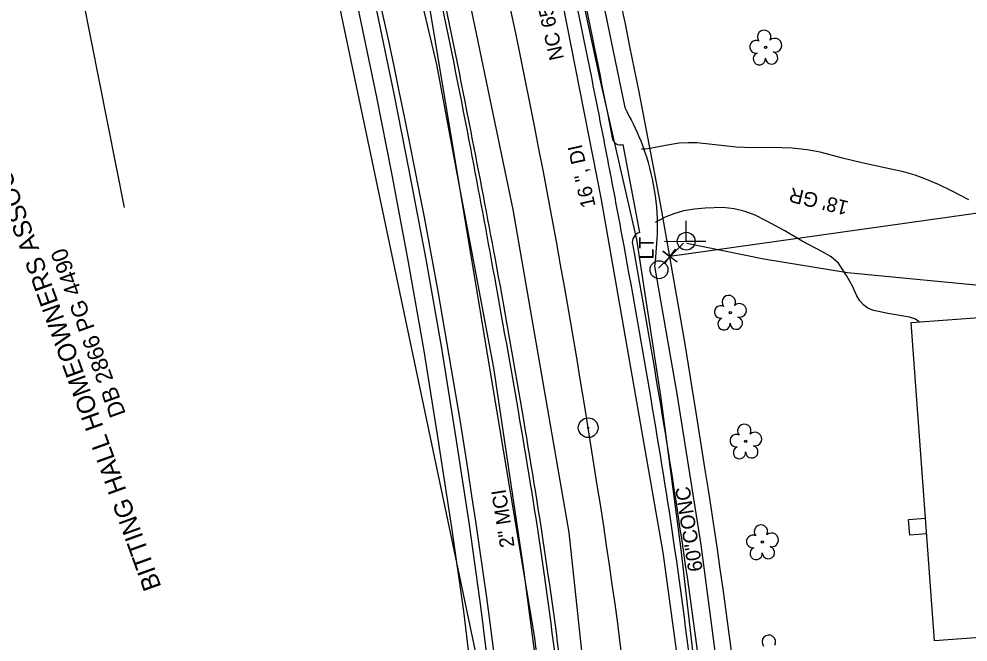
# Model space of a CAD drawing. Extents: x 1614611 to 1617571, y 898867 to 905462.
# Drawn here: x 1616509.7 to 1616770.7, y 902500.2 to 902671.5 of the extents above; entities that cross this region are included whole.
import ezdxf

# ---------------------------------------------------------------- set-up
doc = ezdxf.new("R2010")
doc.units = 0
for name, color, linetype in [('Exist Boundary Watershed Impervious C 09', 7, 'Continuous'), ('Exist Boundary Watershed Residential C 05', 7, 'Continuous'), ('Exist Building', 7, 'Continuous'), ('Exist Horizontal Alignment Tick Label', 7, 'Continuous'), ('Exist Other Culture Area Outline', 7, 'Continuous'), ('Exist Roads EOP Other Text', 7, 'Continuous'), ('Exist Roads EOP Text', 7, 'Continuous'), ('Exist Roads Soil', 7, 'Continuous'), ('Exist Roads Soil Text', 7, 'Continuous'), ('Exist Survey Centerline Point CELL', 7, 'Continuous'), ('Exist Utilities Gas UG Line SUE LOS B', 7, 'Continuous'), ('Exist Utilities Other Pole CELL', 7, 'Continuous'), ('Exist Utilities Other Pole Text', 7, 'Continuous'), ('Exist Utilities Power Joint Use Telephone CELL', 7, 'Continuous'), ('Exist Utilities Telephone UG Cable SUE LOS B', 7, 'Continuous'), ('Exist Utilities Telephone UG FO SUE LOS B', 7, 'Continuous'), ('Exist Utilities Telephone UG FO SUE LOS C', 7, 'Continuous'), ('Exist Utilities Telephone UG FO SUE LOS C Text', 7, 'Continuous'), ('Exist Utilities Water UG Line SUE LOS B', 7, 'Continuous'), ('Exist Utilities Water UG Line SUE LOS B Text', 7, 'Continuous'), ('Exist Vegetation Tree CELL', 7, 'Continuous'), ('Prop Drainage Structure Catch Basin Grate 840 03E Label', 7, 'Continuous'), ('Prop Drainage Structure Pipe Alternate 30in Label', 7, 'Continuous'), ('Prop Drainage Structure Pipe Removal', 7, 'Continuous'), ('Prop Drainage Structure Pipe Removal Label', 7, 'Continuous'), ('Prop Drainage Structure Tops and Inverts LABEL', 7, 'Continuous'), ('Prop Earthen Structure Head Ditch Label', 7, 'Continuous'), ('Raster_Level_2', 7, 'Continuous'), ('Scratch_Level_1', 7, 'Continuous'), ('Scratch_Level_9', 7, 'Continuous')]:
    doc.layers.add(name, color=color, linetype=linetype)

# ---------------------------------------------------------------- blocks, each defined once
blk = doc.blocks.new('EXIST SURVEY CENTERLINE POINT')
at = {"layer": 'Exist Survey Centerline Point CELL'}
for radius in [0.0542, 0.00375]:
    blk.add_circle((0, 0), radius, dxfattribs=at)

msp = doc.modelspace()

# ---------------------------------------------------------------- linework, layer by layer
at = {"layer": 'Exist Boundary Watershed Impervious C 09'}
msp.add_spline([(1616665.13, 902435.43), (1616660.48, 902479.08), (1616654.89, 902521.26), (1616648.51, 902561.33), (1616641.12, 902603.28), (1616634.46, 902638.28), (1616625.9, 902680.69), (1616616.67, 902721.99), (1616606.86, 902763.22), (1616596.71, 902801.99), (1616585.45, 902842.18), (1616573.19, 902881.5), (1616565.19, 902906.61), (1616557.25, 902931.31), (1616544.89, 902968.22), (1616530.94, 903009.35), (1616518.06, 903047.65)], degree=3, dxfattribs=at)
at = {"layer": 'Exist Boundary Watershed Residential C 05'}
for p, q in [((1616671.61, 902645.14), (1616672.82, 902638.84)), ((1616675.8, 902636.98), (1616680.4, 902612.79)), ((1616678.43, 902609.58), (1616678.51, 902609.27))]:
    msp.add_line(p, q, dxfattribs=at)
for centre, major_axis, ratio, start_param, end_param in [((1616675.14, 902639.25), (-2.23, -0.78), 0.999797, 6.125089, 7.800541), ((1616681.13, 902610.14), (0.88, 2.61), 0.999982, 0.589797, 2.101645)]:
    msp.add_ellipse(centre, major_axis=major_axis, ratio=ratio, start_param=start_param, end_param=end_param, dxfattribs=at)
for points in [[(1616609.89, 902892.41), (1616622.17, 902852.43), (1616633.45, 902811.75), (1616643.74, 902771.73), (1616653.39, 902730.67), (1616662.94, 902688.03), (1616671.61, 902645.14)], [(1616678.51, 902609.27), (1616685.77, 902567.51), (1616692.26, 902526.08), (1616698.01, 902483.12), (1616702.89, 902438.1)]]:
    msp.add_spline(points, degree=3, dxfattribs=at)
at = {"layer": 'Exist Building'}
msp.add_lwpolyline([(1616786.91, 902566.36), (1616791.57, 902502.74), (1616761.45, 902500.53), (1616755.04, 902588.07), (1616785.04, 902590.27), (1616785.29, 902586.87), (1616801.91, 902588.09), (1616803.42, 902567.57)], close=True, dxfattribs=at)
at = {"layer": 'Exist Other Culture Area Outline'}
msp.add_lwpolyline([(1616759.3, 902529.96), (1616754.72, 902529.58), (1616754.35, 902533.86), (1616758.98, 902534.25)], dxfattribs=at)
at = {"layer": 'Exist Roads Soil'}
for points in [[(1616770.94, 902621.8), (1616766.35, 902624.21), (1616762.63, 902626.01), (1616759.28, 902627.41), (1616756.2, 902628.57), (1616752.95, 902629.5), (1616747.81, 902630.59), (1616741.51, 902631.96), (1616736.18, 902633.25), (1616730.09, 902634.92), (1616726.5, 902635.55), (1616722.37, 902636.04), (1616716.88, 902636.18), (1616711.55, 902636.08), (1616706.93, 902636.33), (1616700.34, 902637.02), (1616696.17, 902637.47), (1616693.76, 902637.52), (1616691.23, 902637.35), (1616687.54, 902636.74), (1616683.27, 902635.95), (1616681.94, 902635.78), (1616680.92, 902635.71)], [(1616757.26, 902588.23), (1616756.23, 902588.96), (1616754.59, 902589.56), (1616748.67, 902590.59), (1616746.51, 902590.99), (1616744.72, 902591.39), (1616743.2, 902592.04), (1616742.07, 902592.8), (1616740.96, 902594.01), (1616740.11, 902595.42), (1616738.93, 902598.03), (1616737.26, 902600.97), (1616735.93, 902603.09), (1616735.06, 902604.37), (1616733.09, 902606.11), (1616730.67, 902607.47), (1616725.12, 902610.4), (1616720.34, 902613.24), (1616715.35, 902615.95), (1616712.18, 902617.57), (1616709.41, 902618.61), (1616706.41, 902619.33), (1616703.3, 902619.67), (1616698.4, 902619.56), (1616695.5, 902619.2), (1616692.46, 902618.75), (1616689.76, 902617.95), (1616687.43, 902617.03), (1616684.67, 902615.6)]]:
    msp.add_lwpolyline(points, dxfattribs=at)
at = {"layer": 'Exist Utilities Gas UG Line SUE LOS B'}
msp.add_lwpolyline([(1616661.01, 902037.25), (1616663.33, 902064.4), (1616667.18, 902120.35), (1616669.8, 902175.63), (1616670.18, 902203.89), (1616670, 902252.83), (1616667.06, 902308.42), (1616666.18, 902342.89), (1616662.96, 902384.82), (1616659.36, 902418.53), (1616657.17, 902446.04), (1616652.37, 902490.94), (1616648.49, 902520.82), (1616640.31, 902575.63), (1616630.24, 902629.08), (1616624.64, 902659), (1616610.54, 902718.34), (1616603.5, 902747.83), (1616594.95, 902779.96), (1616588.83, 902805.4), (1616574.94, 902856.71), (1616560.06, 902902.39)], dxfattribs=at)
at = {"layer": 'Exist Utilities Other Pole CELL'}
msp.add_circle((1616685.72, 902602.58), 2.46, dxfattribs=at)
at = {"layer": 'Exist Utilities Power Joint Use Telephone CELL'}
msp.add_line((1616693.21, 902610.41), (1616693.21, 902610.41), dxfattribs=at)
msp.add_lwpolyline([(1616687.27, 902610.41), (1616698.61, 902610.38), (1616693.21, 902610.4), (1616693.21, 902616.04)], dxfattribs=at)
msp.add_circle((1616693.21, 902610.42), 2.45, dxfattribs=at)
at = {"layer": 'Exist Utilities Telephone UG Cable SUE LOS B'}
msp.add_lwpolyline([(1616653.58, 902416.71), (1616663.67, 902417.14), (1616669.74, 902418.75), (1616672.64, 902421.54), (1616661.03, 902530.35), (1616645.59, 902619.16), (1616624.26, 902721.72), (1616610.21, 902784.31), (1616604.98, 902794.39), (1616600.3, 902799.85), (1616600.03, 902805.22), (1616598.01, 902825.81), (1616571.3, 902910.94), (1616549.08, 902977.64), (1616515.65, 903076.73), (1616483.43, 903168.54), (1616464.03, 903218.81), (1616463.64, 903219.2), (1616462.93, 903219.33), (1616457.94, 903217.72), (1616449, 903216.46)], dxfattribs=at)
at = {"layer": 'Exist Utilities Telephone UG FO SUE LOS B'}
msp.add_lwpolyline([(1616708.77, 902097.06), (1616709.58, 902140.25), (1616710.58, 902218.49), (1616710.01, 902283.99), (1616708.01, 902353.12), (1616701.91, 902435.97), (1616696.63, 902483.57), (1616691.69, 902526.33), (1616686.21, 902567.93), (1616679.63, 902610.92), (1616669.49, 902655.34), (1616656.06, 902717.52), (1616648.63, 902743.65), (1616630.5, 902815.16), (1616628.69, 902826.2), (1616634.94, 902830.28)], dxfattribs=at)
at = {"layer": 'Exist Utilities Telephone UG FO SUE LOS C'}
for p, q in [((1616538.68, 902619.72), (1616523, 902698.69)), ((1616651.55, 902501.26), (1616620.89, 902685.44)), ((1616659.31, 902433.27), (1616651.55, 902501.26))]:
    msp.add_line(p, q, dxfattribs=at)
at = {"layer": 'Exist Utilities Water UG Line SUE LOS B'}
msp.add_lwpolyline([(1616682.85, 901889.35), (1616688.26, 901932.45), (1616696.61, 902016.19), (1616699.26, 902055.42), (1616702.78, 902110.39), (1616705.34, 902181.72), (1616707.31, 902255.35), (1616706.62, 902316.75), (1616703.14, 902377.45), (1616699.12, 902434.84), (1616686.86, 902524.85), (1616669.78, 902622.34), (1616658.13, 902681.62), (1616634.87, 902784.56), (1616617.17, 902853.52), (1616602.15, 902900.61), (1616584.28, 902954.24), (1616571.86, 902993.81)], dxfattribs=at)
at = {"layer": 'Exist Vegetation Tree CELL'}
for p, q in [((1616715.02, 902663.73), (1616715.02, 902663.73)), ((1616705.3, 902590.8), (1616705.3, 902590.8)), ((1616709.57, 902555.4), (1616709.57, 902555.4)), ((1616714.14, 902527.68), (1616714.14, 902527.68))]:
    msp.add_line(p, q, dxfattribs=at)
for centre in [(1616715.02, 902663.73), (1616705.3, 902590.8), (1616709.57, 902555.4), (1616714.14, 902527.68)]:
    msp.add_circle(centre, 0.326, dxfattribs=at)
for centre, radius, start, end in [((1616714.64, 902666.61), 1.86, 330.1651, 219.7134), ((1616712.42, 902663.89), 1.73, 62.6636, 279.3457), ((1616717.57, 902664.32), 1.9, 257.1011, 134.1999), ((1616713.32, 902660.61), 1.69, 111.5671, 6.231), ((1616716.69, 902660.84), 1.7, 181.2822, 74.56), ((1616704.92, 902593.68), 1.86, 330.1651, 219.7134), ((1616702.7, 902590.96), 1.73, 62.6636, 279.3457), ((1616707.85, 902591.39), 1.9, 257.1011, 134.1999), ((1616703.6, 902587.68), 1.69, 111.5671, 6.231), ((1616706.98, 902587.9), 1.7, 181.2822, 74.56), ((1616709.18, 902558.27), 1.86, 330.1651, 219.7134), ((1616706.96, 902555.56), 1.73, 62.6636, 279.3457), ((1616712.12, 902555.99), 1.9, 257.1011, 134.1999), ((1616707.86, 902552.28), 1.69, 111.5671, 6.231), ((1616711.24, 902552.5), 1.7, 181.2822, 74.56), ((1616713.76, 902530.56), 1.86, 330.1651, 219.7134), ((1616716.69, 902528.27), 1.9, 257.1011, 134.1999), ((1616711.54, 902527.84), 1.73, 62.6636, 279.3457), ((1616712.44, 902524.56), 1.69, 111.5671, 6.231), ((1616715.81, 902524.78), 1.7, 181.2822, 74.56), ((1616715.92, 902500.25), 1.86, 330.1651, 219.7134)]:
    msp.add_arc(centre, radius, start, end, dxfattribs=at)
at = {"layer": 'Prop Drainage Structure Catch Basin Grate 840 03E Label'}
msp.add_line((1616685.62, 902602.97), (1616692.49, 902609.9), dxfattribs=at)
msp.add_lwpolyline([(1616787.05, 902562.49), (1616788.6, 902564.35), (1616789.39, 902593.01), (1616785.63, 902596.22), (1616779.42, 902597.73), (1616737.56, 902601.75), (1616714.59, 902605.5), (1616693.38, 902609.8)], dxfattribs=at)
at = {"layer": 'Prop Drainage Structure Pipe Alternate 30in Label'}
msp.add_line((1616930.47, 902640.34), (1616688.73, 902606.22), dxfattribs=at)
at = {"layer": 'Prop Drainage Structure Tops and Inverts LABEL'}
msp.add_line((1616688.73, 902606.22), (1616688.73, 902606.22), dxfattribs=at)
msp.add_lwpolyline([(1616687.22, 902604.22), (1616690.23, 902608.21), (1616688.73, 902606.22), (1616686.73, 902607.72), (1616690.72, 902604.71)], dxfattribs=at)
at = {"layer": 'Prop Earthen Structure Head Ditch Label'}
for p, q in [((1616010.65, 905462.23), (1616993.32, 900797.76)), ((1616698.46, 902547.52), (1616695.86, 902563.86))]:
    msp.add_line(p, q, dxfattribs=at)
for centre, radius, start, end in [((1614325.74, 902186.35), 2400, 9.05, 18.76383), ((1614538.44, 902221.24), 2120, 353.93806, 18.41557), ((1615052.19, 902285.31), 1667.02, 2.98333, 9.05)]:
    msp.add_arc(centre, radius, start, end, dxfattribs=at)
at = {"layer": 'Raster_Level_2'}
msp.add_line((1616668.84, 902542.8), (1616666.24, 902559.14), dxfattribs=at)
for centre, radius, start, end in [((1614346.11, 902189.59), 2349.37, 9.05, 19.17682), ((1615052.19, 902285.31), 1637.02, 2.98333, 9.05)]:
    msp.add_arc(centre, radius, start, end, dxfattribs=at)
at = {"layer": 'Scratch_Level_1'}
for points in [[(1616614.65, 902893.86), (1616626.96, 902853.56), (1616638.24, 902812.83), (1616648.55, 902772.75), (1616658.26, 902731.61), (1616667.73, 902688.88), (1616676.31, 902647.23)], [(1616635.2, 902482.65), (1616632, 902508.68), (1616628.75, 902531.69), (1616625.18, 902554.85), (1616621.17, 902580.26), (1616616.86, 902604.66), (1616612.24, 902629.12), (1616608.13, 902650.05), (1616602.88, 902675.06), (1616598.15, 902696.53), (1616592.96, 902718.62), (1616589.01, 902735.14), (1616584.24, 902754.42)], [(1616640.05, 902483.2), (1616636.84, 902509.29), (1616633.58, 902532.38), (1616630.01, 902555.58), (1616625.98, 902581.04), (1616621.66, 902605.52), (1616617.03, 902630.01), (1616612.92, 902650.99), (1616607.66, 902676.06), (1616602.92, 902697.58), (1616597.72, 902719.72), (1616593.76, 902736.26), (1616588.99, 902755.56)], [(1616684.52, 902603.59), (1616690.62, 902568.42), (1616697.25, 902526.88), (1616702.9, 902483.76), (1616707.92, 902438.46)]]:
    msp.add_lwpolyline(points, dxfattribs=at)
msp.add_spline([(1616676.31, 902647.23), (1616680.68, 902638), (1616685.21, 902613.58), (1616684.52, 902603.59)], degree=3, dxfattribs=at)
at = {"layer": 'Scratch_Level_9'}
for points in [[(1616664.02, 902435.24), (1616659.23, 902479.02), (1616653.86, 902521.19), (1616647.48, 902561.19), (1616640.05, 902603.13), (1616633.52, 902638.17), (1616624.95, 902680.56), (1616615.82, 902721.84), (1616606.01, 902763.05), (1616595.75, 902801.7), (1616584.26, 902841.93), (1616572.3, 902881.24), (1616564.26, 902906.37), (1616556.43, 902931.12), (1616543.99, 902967.9), (1616530.08, 903008.97), (1616517.05, 903047.39)], [(1616607.54, 902891.47), (1616619.8, 902851.65), (1616630.95, 902811.11), (1616641.26, 902771.18), (1616651.06, 902730.14), (1616660.51, 902687.43), (1616669.23, 902644.79), (1616673.27, 902623.83), (1616676.02, 902609.12), (1616683.43, 902567.11), (1616690.02, 902525.73), (1616695.57, 902482.82), (1616700.47, 902437.88)]]:
    msp.add_spline(points, degree=3, dxfattribs=at)

# ---------------------------------------------------------------- block references
at = {"layer": 'Exist Horizontal Alignment Tick Label', "xscale": 50, "yscale": 50, "rotation": 1.7967031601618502e-12}
msp.add_blockref('EXIST SURVEY CENTERLINE POINT', (1616666.24, 902559.14), dxfattribs=at)

# ---------------------------------------------------------------- texts
at = {"layer": 'Exist Roads EOP Other Text'}
msp.add_text('60"CONC', height=4, rotation=99.0568, dxfattribs=at).set_placement((1616697.8, 902519.89))
at = {"layer": 'Exist Roads EOP Text'}
msp.add_text('NC 65 BETHANIA RURAL HALL RD.', height=4, rotation=102.4863, dxfattribs=at).set_placement((1616659.6, 902660.68))
at = {"layer": 'Exist Roads Soil Text'}
msp.add_text("18' GR", height=4, rotation=166.3479, dxfattribs=at).set_placement((1616738.1, 902621.35))
at = {"layer": 'Exist Utilities Other Pole Text'}
msp.add_text('LT', height=4, rotation=90, dxfattribs=at).set_placement((1616684.24, 902605.38))
at = {"layer": 'Exist Utilities Telephone UG FO SUE LOS C Text'}
msp.add_text('2" MCI', height=4, rotation=98.9923, dxfattribs=at).set_placement((1616646.01, 902526.48))
at = {"layer": 'Exist Utilities Water UG Line SUE LOS B Text'}
msp.add_text('16 ", DI', height=4, rotation=102.7308, dxfattribs=at).set_placement((1616668.3, 902620.1))
at = {"layer": 'Prop Drainage Structure Pipe Removal'}
msp.add_text('BITTING HALL HOMEOWNERS ASSOCIATION INC.', height=5, rotation=109.8901, dxfattribs=at).set_placement((1616548.89, 902515.39))
at = {"layer": 'Prop Drainage Structure Pipe Removal Label'}
msp.add_text('DB 2866 PG 4490', height=4.5, rotation=109.8901, dxfattribs=at).set_placement((1616539.12, 902562.98))

doc.saveas('drawing.dxf')
